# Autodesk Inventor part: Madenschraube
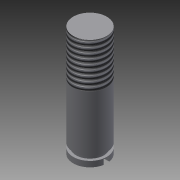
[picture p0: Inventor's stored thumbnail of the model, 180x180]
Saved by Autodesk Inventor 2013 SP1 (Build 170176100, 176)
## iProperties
Created: 2012-11
Part Number: Madenschraube
Material: Allgemein
Document SubType Name: Modeling
Designer: s0536599
Density: 1 g/cm^3
Author: s0536599
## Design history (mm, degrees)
sketch "Skizze1"
  geometry: L1 (0, -7.9)-(0, 47.4) reference; L2 (7.2, 0)-(-1.2, 0) reference; L3 (0, 0)-(6, 0); L4 (6, 0)-(6, 2); L5 (6, 2)-(5, 2); L6 (5, 2)-(5, 3.5); L7 (5, 3.5)-(6, 3.5); L8 (6, 3.5)-(6, 39.5); L9 (6, 39.5)-(0, 39.5); L10 (0, 39.5)-(0, 0)
  constraints: 16 end point, 4 perpendicular, 2 parallel, 2 point on line, 1 collinear
  dimensions: "d4" = 6 distance of L3.start L3.end; "d5" = 2 distance of L3.end L4.end; "d6" = 1 distance of L4.end L5.end; "d7" = 1.5 distance of L5.end L6.end; "d8" = 36 distance of L7.end L8.end; "d9" = 6 distance between parallel lines of L10 L8
revolve "Umdrehung1" sketch "Skizze1" stored, may be unused: angle "d10" = 90 deg
feature "Gewinde1" dims "d11" = 16, "d12" = 20
workplane "Arbeitsebene5"
sketch "Skizze7"
  geometry: L1 (0, -21.5)-(1, -21.5); L2 (1, -21.5)-(0, -21.5); L3 (0, -21.5)-(-1, -21.5); L4 (-1, -21.5)-(-1, -19.7); L5 (-1, -19.7)-(1, -19.7); L6 (1, -19.7)-(1, -21.5)
  constraints: 12 end point, 2 collinear, 2 parallel, 1 horizontal, 1 perpendicular
  dimensions: "d30" = 1 distance of L1.start L1.end; "d31" = 1 distance of L1.start L3.end; "d32" = 1.8 distance of L3.end L4.end
extrude "Extrusion3" cut sketch "Skizze7" distance "d33" = 12; taper "d34" = 0 deg
node "Volumenkörper1"
